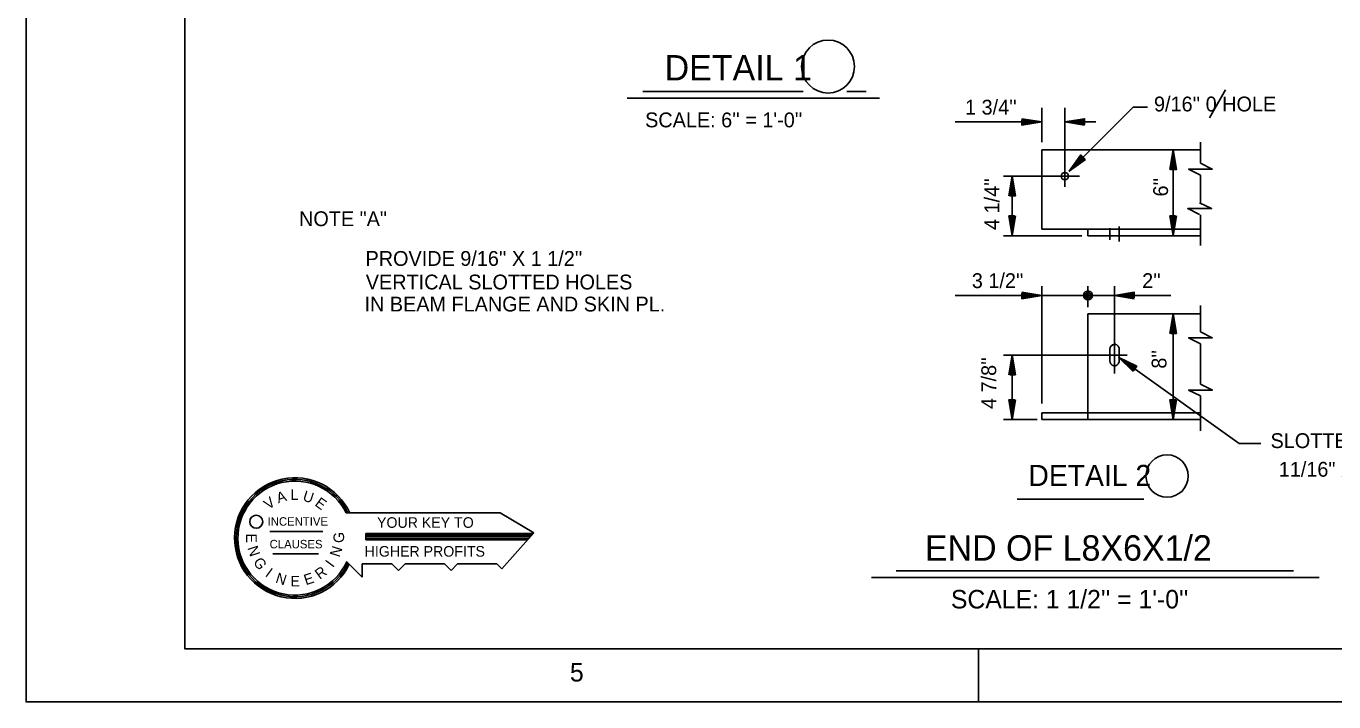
# Model space of a CAD drawing. Extents: x 0.1 to 13.5, y 0.1 to 9.5.
# Drawn here: x 0.125 to 4.244, y 0.125 to 2.253 of the extents above; entities that cross this region are included whole.
import ezdxf

# ---------------------------------------------------------------- set-up
doc = ezdxf.new("R2010")
doc.units = 0
for name, color, linetype in [('Level 1', 7, 'Continuous'), ('Level 13', 7, 'Continuous'), ('Level 25', 7, 'Continuous'), ('Level 3', 7, 'Continuous'), ('Level 50', 7, 'Continuous')]:
    doc.layers.add(name, color=color, linetype=linetype)

msp = doc.modelspace()

# ---------------------------------------------------------------- linework, layer by layer
at = {"layer": 'Level 1'}
for p, q in [((1.1329, 0.7197), (1.6185, 0.7197)), ((1.7245, 0.657), (1.6185, 0.7197)), ((0.8929, 0.6613), (1.0592, 0.6613)), ((1.7232, 0.6553), (1.1945, 0.6553)), ((1.1945, 0.6553), (1.1945, 0.6347)), ((1.7179, 0.6497), (1.1945, 0.6497)), ((1.7132, 0.6443), (1.1945, 0.6443)), ((1.7082, 0.6387), (1.1945, 0.6387)), ((1.1945, 0.6347), (1.7045, 0.6347)), ((1.7245, 0.657), (1.6235, 0.544)), ((0.9015, 0.591), (1.0455, 0.591)), ((1.1352, 0.5663), (1.1835, 0.518)), ((1.1835, 0.518), (1.1835, 0.5597)), ((1.1835, 0.5597), (1.2772, 0.5597)), ((1.2772, 0.5597), (1.2979, 0.539)), ((1.2979, 0.539), (1.3185, 0.5597)), ((1.3185, 0.5597), (1.4425, 0.5597)), ((1.4425, 0.5597), (1.4632, 0.539)), ((1.4632, 0.539), (1.4839, 0.5597)), ((1.4839, 0.5597), (1.6079, 0.5597)), ((1.6079, 0.5597), (1.6235, 0.544)), ((3.125, 0.2917), (3.125, 0.125))]:
    msp.add_line(p, q, dxfattribs=at)
for points in [[(0.125, 9.4583), (13.4583, 9.4583), (13.4583, 0.125), (0.125, 0.125)], [(0.625, 9.2917), (13.2917, 9.2917), (13.2917, 0.2917), (0.625, 0.2917)]]:
    msp.add_lwpolyline(points, close=True, dxfattribs=at)
msp.add_circle((0.8497, 0.6922), 0.0205, dxfattribs=at)
for radius, start, end in [(0.19, 24.569, 334.4243), (0.1848, 25.3095, 334.4522), (0.1796, 26.0896, 335.5943)]:
    msp.add_arc((0.9715, 0.6407), radius, start, end, dxfattribs=at)
at = {"layer": 'Level 13'}
for points in [[(3.8237, 1.8213), (3.8612, 1.8026), (3.7863, 1.8026), (3.8237, 1.7839)], [(3.8213, 1.6968), (3.8588, 1.6781), (3.7839, 1.6781), (3.8213, 1.6594)], [(3.8237, 1.2903), (3.8612, 1.2716), (3.7863, 1.2716), (3.8237, 1.2529)], [(3.8238, 1.1256), (3.8613, 1.1069), (3.7864, 1.1069), (3.8238, 1.0882)]]:
    msp.add_lwpolyline(points, dxfattribs=at)
at = {"layer": 'Level 25'}
for p, q in [((3.8523, 1.9646), (3.9031, 2.0525)), ((3.3238, 1.9953), (3.3238, 1.8871)), ((3.3967, 1.9953), (3.3967, 1.7468)), ((3.3238, 1.951), (3.0513, 1.951)), ((3.3967, 1.951), (3.4942, 1.951)), ((3.3238, 1.8637), (3.8238, 1.8637)), ((3.3238, 1.8637), (3.3238, 1.6137)), ((3.7377, 1.8637), (3.7377, 1.5928)), ((3.8238, 1.8877), (3.8238, 1.8212)), ((3.2038, 1.7803), (3.4425, 1.7803)), ((3.2309, 1.7803), (3.2309, 1.5928)), ((3.8238, 1.7839), (3.8238, 1.6955)), ((3.8238, 1.7253), (3.8238, 1.7253)), ((3.8238, 1.7253), (3.8238, 1.7123)), ((3.8238, 1.6582), (3.8238, 1.5616)), ((3.3238, 1.6137), (3.8238, 1.6137)), ((3.4696, 1.6137), (3.4696, 1.5928)), ((3.5386, 1.6165), (3.5386, 1.5801)), ((3.5673, 1.6217), (3.5673, 1.5748)), ((3.4499, 1.5928), (3.2038, 1.5928)), ((3.4696, 1.5928), (3.8238, 1.5928)), ((3.3238, 1.4047), (3.0513, 1.4047)), ((3.3238, 1.065), (3.3238, 1.4342)), ((3.3238, 1.4047), (3.4696, 1.4047)), ((3.4696, 1.4342), (3.4696, 1.3677)), ((3.4696, 1.4047), (3.4696, 1.4047)), ((3.4696, 1.4047), (3.5529, 1.4047)), ((3.5529, 1.1585), (3.5529, 1.4342)), ((3.7304, 1.4047), (3.5529, 1.4047)), ((3.8238, 1.2902), (3.8238, 1.3733)), ((3.4696, 1.3474), (3.8238, 1.3474)), ((3.4696, 1.0141), (3.4696, 1.3474)), ((3.7377, 1.0141), (3.7377, 1.3474)), ((3.5542, 1.251), (3.5568, 1.251)), ((3.5673, 1.1937), (3.5673, 1.2406)), ((3.8238, 1.1256), (3.8238, 1.2529)), ((3.2038, 1.2172), (3.5926, 1.2172)), ((3.2309, 1.0141), (3.2309, 1.2172)), ((3.5386, 1.1989), (3.5386, 1.2354)), ((3.5542, 1.1833), (3.5568, 1.1833)), ((3.8238, 1.1799), (3.8238, 1.1799)), ((3.8238, 0.9783), (3.8238, 1.0882)), ((3.3238, 1.0141), (3.3238, 1.0349)), ((3.3238, 1.0349), (3.4696, 1.0349)), ((3.8238, 1.0349), (3.4696, 1.0349)), ((3.2038, 1.0141), (3.3096, 1.0141)), ((3.3238, 1.0141), (3.8238, 1.0141))]:
    msp.add_line(p, q, dxfattribs=at)
msp.add_circle((3.3967, 1.7803), 0.0117, dxfattribs=at)
for centre, radius, start, end in [((3.5532, 1.2364), 0.0146, 16.645, 183.9647), ((3.5542, 1.2354), 0.0156, 90, 180), ((3.5532, 1.1979), 0.0146, 176.0353, 343.355)]:
    msp.add_arc(centre, radius, start, end, dxfattribs=at)
at = {"layer": 'Level 3'}
for p, q in [((2.8133, 2.0259), (2.0184, 2.0259)), ((2.0673, 2.0467), (2.5725, 2.0467)), ((2.771, 2.0467), (2.7104, 2.0467)), ((3.4105, 1.796), (3.4105, 1.796)), ((3.4228, 1.8083), (3.4228, 1.8083)), ((3.5667, 1.2096), (3.5667, 1.2096)), ((3.5808, 1.1995), (3.5808, 1.1995)), ((3.2469, 0.7629), (3.6455, 0.7629)), ((2.8656, 0.5373), (4.1167, 0.5373)), ((4.1975, 0.5165), (2.7876, 0.5165))]:
    msp.add_line(p, q, dxfattribs=at)
for points in [[(3.6565, 1.9978), (3.6123, 1.9978), (3.4105, 1.796)], [(3.4619, 1.8328), (3.4105, 1.796), (3.4473, 1.8474), (3.4598, 1.8349), (3.4228, 1.8083), (3.4477, 1.8431), (3.4558, 1.8351), (3.4345, 1.82), (3.4482, 1.8389), (3.4515, 1.8356), (3.4468, 1.8323)], [(4.0145, 0.9389), (3.9456, 0.9389), (3.5667, 1.2096)], [(3.6114, 1.1649), (3.5667, 1.2096), (3.6234, 1.1818), (3.6132, 1.1674), (3.5808, 1.1995), (3.6193, 1.1806), (3.6128, 1.1714), (3.5944, 1.1898), (3.6152, 1.1794), (3.6125, 1.1756), (3.6085, 1.1798)]]:
    msp.add_lwpolyline(points, dxfattribs=at)
for centre, radius in [((2.6508, 2.1255), 0.0833), ((3.7187, 0.836), 0.0667)]:
    msp.add_circle(centre, radius, dxfattribs=at)
at = {"layer": 'Level 50'}
for p, q in [((3.3064, 1.951), (3.3064, 1.951)), ((3.3238, 1.951), (3.3238, 1.951)), ((3.3967, 1.951), (3.3967, 1.951)), ((3.414, 1.951), (3.414, 1.951)), ((3.7377, 1.8637), (3.7377, 1.8637)), ((3.7377, 1.8463), (3.7377, 1.8463)), ((3.2309, 1.7803), (3.2309, 1.7803)), ((3.2309, 1.763), (3.2309, 1.763)), ((3.2309, 1.6102), (3.2309, 1.6102)), ((3.7377, 1.6102), (3.7377, 1.6102)), ((3.2309, 1.5928), (3.2309, 1.5928)), ((3.7377, 1.5928), (3.7377, 1.5928)), ((3.3064, 1.4047), (3.3064, 1.4047)), ((3.3238, 1.4047), (3.3238, 1.4047)), ((3.5529, 1.4047), (3.5529, 1.4047)), ((3.5703, 1.4047), (3.5703, 1.4047)), ((3.7377, 1.3474), (3.7377, 1.3474)), ((3.7377, 1.3301), (3.7377, 1.3301)), ((3.2309, 1.2172), (3.2309, 1.2172)), ((3.2309, 1.1998), (3.2309, 1.1998)), ((3.2309, 1.0314), (3.2309, 1.0314)), ((3.7377, 1.0314), (3.7377, 1.0314)), ((3.2309, 1.0141), (3.2309, 1.0141)), ((3.7377, 1.0141), (3.7377, 1.0141))]:
    msp.add_line(p, q, dxfattribs=at)
for points in [[(3.2614, 1.9614), (3.3238, 1.951), (3.2614, 1.9407), (3.2614, 1.9584), (3.3064, 1.951), (3.2641, 1.944), (3.2641, 1.9554), (3.2898, 1.951), (3.2668, 1.9474), (3.2668, 1.952), (3.2724, 1.951)], [(3.459, 1.9407), (3.3967, 1.951), (3.459, 1.9614), (3.459, 1.9437), (3.414, 1.951), (3.4564, 1.958), (3.4564, 1.9467), (3.4307, 1.951), (3.4537, 1.9547), (3.4537, 1.95), (3.448, 1.951)], [(3.7274, 1.8013), (3.7377, 1.8637), (3.7481, 1.8013), (3.7304, 1.8013), (3.7377, 1.8463), (3.7447, 1.804), (3.7334, 1.804), (3.7377, 1.8297), (3.7414, 1.8067), (3.7367, 1.8067), (3.7377, 1.8123)], [(3.2206, 1.718), (3.2309, 1.7803), (3.2412, 1.718), (3.2236, 1.718), (3.2309, 1.763), (3.2379, 1.7207), (3.2266, 1.7207), (3.2309, 1.7463), (3.2346, 1.7233), (3.2299, 1.7233), (3.2309, 1.729)], [(3.2412, 1.6552), (3.2309, 1.5928), (3.2206, 1.6552), (3.2382, 1.6552), (3.2309, 1.6102), (3.2239, 1.6525), (3.2352, 1.6525), (3.2309, 1.6268), (3.2272, 1.6498), (3.2319, 1.6498), (3.2309, 1.6442)], [(3.7481, 1.6552), (3.7377, 1.5928), (3.7274, 1.6552), (3.7451, 1.6552), (3.7377, 1.6102), (3.7307, 1.6525), (3.7421, 1.6525), (3.7377, 1.6268), (3.7341, 1.6498), (3.7387, 1.6498), (3.7377, 1.6442)], [(3.2614, 1.415), (3.3238, 1.4047), (3.2614, 1.3943), (3.2614, 1.412), (3.3064, 1.4047), (3.2641, 1.3977), (3.2641, 1.409), (3.2898, 1.4047), (3.2668, 1.401), (3.2668, 1.4057), (3.2724, 1.4047)], [(3.6153, 1.3943), (3.5529, 1.4047), (3.6153, 1.415), (3.6153, 1.3973), (3.5703, 1.4047), (3.6126, 1.4117), (3.6126, 1.4003), (3.5869, 1.4047), (3.6099, 1.4083), (3.6099, 1.4037), (3.6043, 1.4047)], [(3.7274, 1.2851), (3.7377, 1.3474), (3.7481, 1.2851), (3.7304, 1.2851), (3.7377, 1.3301), (3.7447, 1.2877), (3.7334, 1.2877), (3.7377, 1.3134), (3.7414, 1.2904), (3.7367, 1.2904), (3.7377, 1.2961)], [(3.2206, 1.1548), (3.2309, 1.2172), (3.2412, 1.1548), (3.2236, 1.1548), (3.2309, 1.1998), (3.2379, 1.1575), (3.2266, 1.1575), (3.2309, 1.1832), (3.2346, 1.1602), (3.2299, 1.1602), (3.2309, 1.1658)], [(3.2412, 1.0764), (3.2309, 1.0141), (3.2206, 1.0764), (3.2382, 1.0764), (3.2309, 1.0314), (3.2239, 1.0737), (3.2352, 1.0737), (3.2309, 1.0481), (3.2272, 1.0711), (3.2319, 1.0711), (3.2309, 1.0654)], [(3.7481, 1.0764), (3.7377, 1.0141), (3.7274, 1.0764), (3.7451, 1.0764), (3.7377, 1.0314), (3.7307, 1.0737), (3.7421, 1.0737), (3.7377, 1.0481), (3.7341, 1.0711), (3.7387, 1.0711), (3.7377, 1.0654)]]:
    msp.add_lwpolyline(points, dxfattribs=at)
for radius in [0.0141, 0.00879, 0.00352]:
    msp.add_circle((3.4696, 1.4047), radius, dxfattribs=at)

# ---------------------------------------------------------------- texts
at = {"layer": 'Level 1'}
for s, height, p in [('IN BEAM FLANGE AND SKIN PL.', 0.046698, (1.1907, 1.3543)), ('L', 0.0333, (0.9579, 0.761)), ('INCENTIVE', 0.02667, (0.8855, 0.6797)), ('YOUR KEY TO', 0.033333, (1.2302, 0.673)), ('CLAUSES', 0.02667, (0.8919, 0.6083)), ('HIGHER PROFITS', 0.033333, (1.1912, 0.5823)), ('E', 0.0333, (0.9572, 0.4883)), ('5', 0.0584, (1.8378, 0.189))]:
    msp.add_text(s, height=height, dxfattribs=at).set_placement(p)
for s, rotation, p in [('A', 18.0731, (0.9195, 0.75)), ('U', 342.1107, (0.9939, 0.7597)), ('V', 35.9204, (0.8885, 0.7287)), ('E', 323.9298, (1.0319, 0.7447)), ('E', 270, (0.8179, 0.6553)), ('G', 90, (1.1265, 0.6253)), ('N', 288.0821, (0.8215, 0.61)), ('G', 306.0537, (0.8385, 0.5647)), ('N', 71.9179, (1.1119, 0.5783)), ('I', 323.5836, (0.8755, 0.5223)), ('R', 36.2206, (1.0499, 0.509)), ('I', 53.5836, (1.0912, 0.5457)), ('N', 341.9179, (0.9082, 0.5013)), ('E', 18.2241, (1.0062, 0.492))]:
    msp.add_text(s, height=0.0333, rotation=rotation, dxfattribs=at).set_placement(p)
at = {"layer": 'Level 25'}
for s, height, p in [("1 3/4''", 0.0467, (3.0823, 1.9743)), ("9/16'' 0 HOLE", 0.046698, (3.6775, 1.9843)), ("SCALE: 6'' = 1'-0''", 0.046698, (2.0746, 1.9342)), ('NOTE "A"', 0.0467, (0.9846, 1.623)), ("PROVIDE 9/16'' X 1 1/2''", 0.046698, (1.194, 1.4979)), ('VERTICAL SLOTTED HOLES', 0.046698, (1.1948, 1.4237)), ("3 1/2''", 0.0467, (3.1037, 1.428)), ("2''", 0.0467, (3.6402, 1.428)), ('SLOTTED HOLE', 0.046698, (4.0446, 0.9241)), ('11/16" X 1 7/8"', 0.046698, (4.0705, 0.834)), ("SCALE: 1 1/2'' = 1'-0''", 0.058292, (3.0378, 0.4191))]:
    msp.add_text(s, height=height, dxfattribs=at).set_placement(p)
for s, p in [("6''", (3.7217, 1.7163)), ("4 1/4''", (3.1903, 1.611)), ("4 7/8''", (3.1804, 1.0473)), ("8''", (3.7168, 1.1742))]:
    msp.add_text(s, height=0.0467, rotation=90, dxfattribs=at).set_placement(p)
at = {"layer": 'Level 3'}
for s, height, p in [('DETAIL 1', 0.08, (2.1361, 2.0818)), ('DETAIL 2', 0.0667, (3.2819, 0.8046)), ('END OF L8X6X1/2', 0.08, (2.9559, 0.5696))]:
    msp.add_text(s, height=height, dxfattribs=at).set_placement(p)

doc.saveas('drawing.dxf')
